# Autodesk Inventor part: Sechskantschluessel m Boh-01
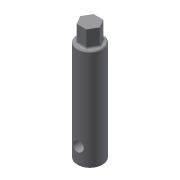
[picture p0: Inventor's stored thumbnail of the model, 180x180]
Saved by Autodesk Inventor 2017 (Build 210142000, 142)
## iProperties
Created: 2015-06
Part Number: Sechskantschluessel m Boh-01
Material: Generisch
Document SubType Name: Modeling
Designer: e_krauts
Density: 1 g/cm^3
Appearance: Vorgabe
Author: e_krauts
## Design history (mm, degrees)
sketch "Skizze1"
  geometry: C1 r 7.5 at (0, 0); 1 further point
  constraints: 1 centre point, 1 coincident
  dimensions: "d0" = 15 diameter of C1
extrude "Extrusion1" new body sketch "Skizze1" distance "d1" = 60; taper "d2" = 0 deg
workplane "Arbeitsebene1"
sketch "Skizze2"
  geometry: L1 (-7.5, 0)-(7.5, 0) reference; 2 further points
  dimensions: "d3" = 10 distance from line of point (0, 10) L1
hole "Bohrung1" sketch "Skizze2" diameter "d4" = 6.2; stored, may be unused: countersink angle "d8" = 90 deg, drill point angle "d10" = 118 deg; dims "d5" = 6, "d6" = 4, "d7" = 2, "d9" = 8
sketch "Skizze3"
  geometry: L1 (2.887, -5)-(-2.887, -5); L2 (-2.887, -5)-(-5.774, 0); L3 (-5.774, 0)-(-2.887, 5); L4 (-2.887, 5)-(2.887, 5); L5 (2.887, 5)-(5.774, 0); L6 (5.774, 0)-(2.887, -5); C1 r 7.5 at (0, 0) reference; 1 further point
  constraints: 12 end point, 1 coincident, 1 horizontal, 13 other
  dimensions: "d11" = 10 distance between parallel lines of L1 L4
extrude "Extrusion2" join sketch "Skizze3" distance "d12" = 10; taper "d13" = 0 deg
chamfer "Fase1" distance "d14" = 0.5; stored, may be unused: second distance "d15" = 2, angle "d16" = 45 deg
fillet "Rundung1" dims "d17" = 1
chamfer "Fase2" distance "d18" = 0.5; stored, may be unused: second distance "d19" = 2, angle "d20" = 45 deg
hole "Bohrung2" sketch "Skizze2" diameter "d21" = 4.917; stored, may be unused: countersink angle "d25" = 90 deg, drill point angle "d27" = 118 deg; dims "d22" = 6, "d23" = 4, "d24" = 2, "d26" = 8
node "Volumenkörper1"
